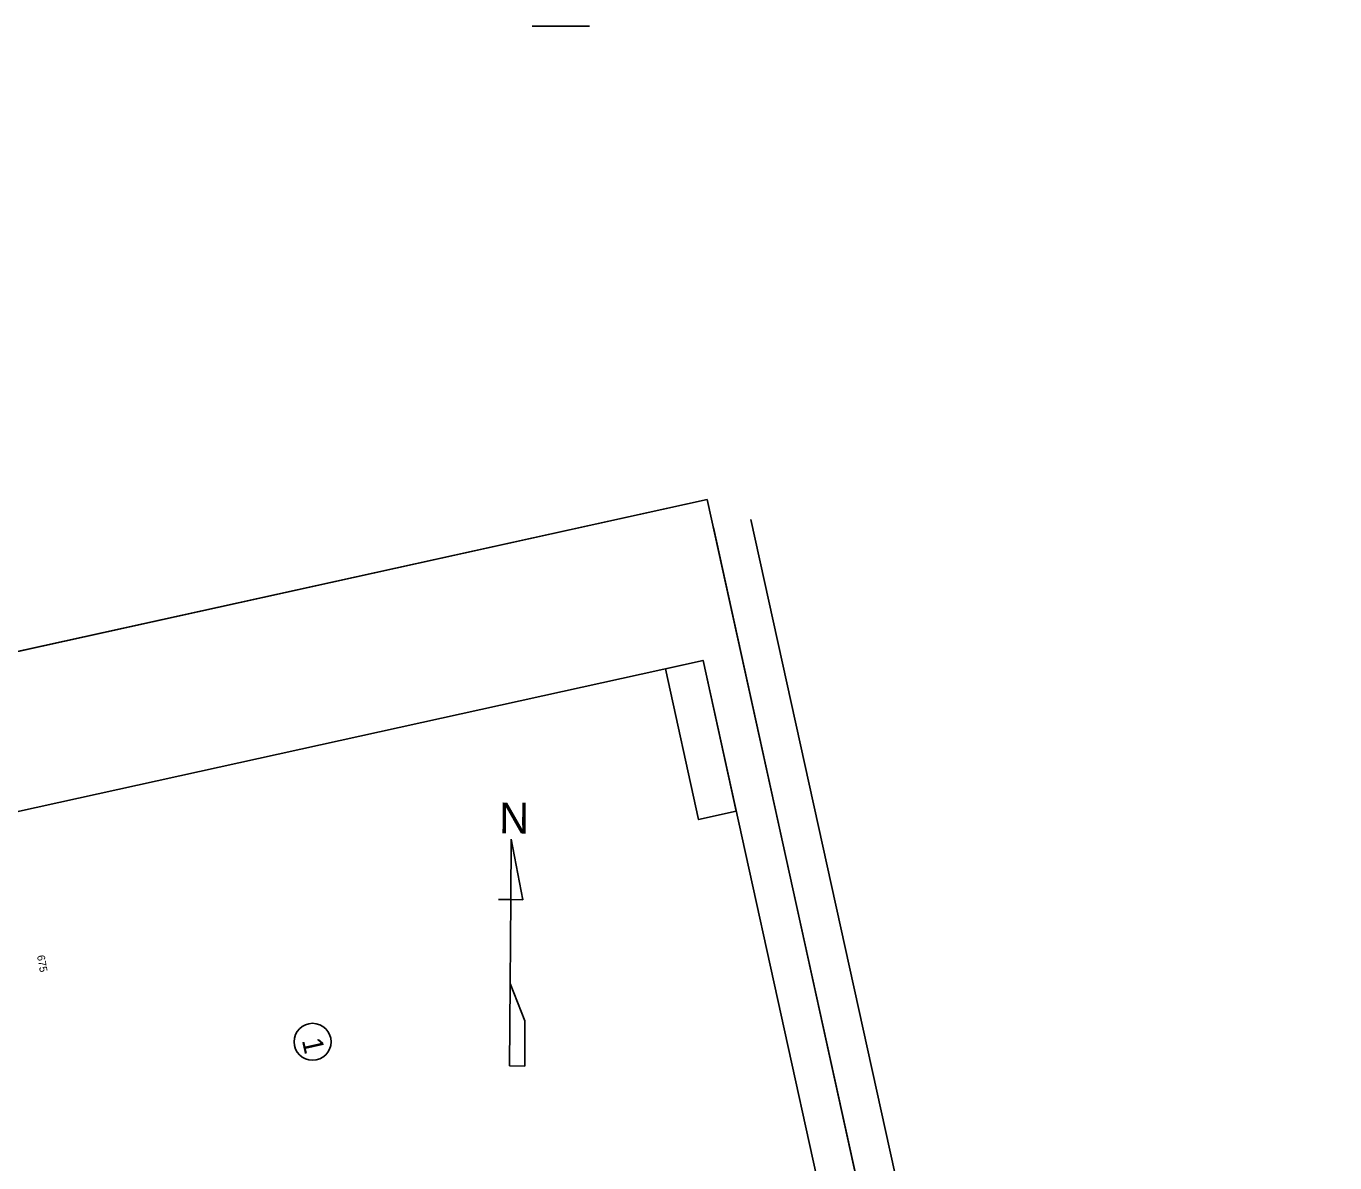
# Model space of a CAD drawing. Extents: x 2521558 to 2525396, y 882711 to 887632.
# Drawn here: x 2523699 to 2525396, y 885971 to 887444 of the extents above; entities that cross this region are included whole.
import ezdxf

# ---------------------------------------------------------------- set-up
doc = ezdxf.new("R2010")
doc.units = 0
for name, color, linetype in [('RD_EX_H2O', 7, 'Continuous'), ('RD_HC_TX_Sta50', 7, 'Continuous'), ('RD_SHT_Bndy', 7, 'Continuous'), ('RD_SHT_IplotShp', 7, 'Continuous'), ('RD_SHT_Snap', 7, 'Continuous'), ('RD_Sketch3', 7, 'Continuous')]:
    doc.layers.add(name, color=color, linetype=linetype)

msp = doc.modelspace()

# ---------------------------------------------------------------- linework, layer by layer
at = {"layer": 'RD_EX_H2O'}
msp.add_line((2524429.3, 887443.8), (2524354.9, 887443.8), dxfattribs=at)
at = {"layer": 'RD_SHT_Bndy'}
for p, q in [((2525395.7, 883367), (2524638.7, 886804.6)), ((2525346.9, 883356.2), (2524589.9, 886793.9)), ((2524576.6, 886621.8), (2522525.7, 886170.2)), ((2525297, 883350.2), (2524576.6, 886621.8))]:
    msp.add_line(p, q, dxfattribs=at)
msp.add_lwpolyline([(2524527.8, 886610.9), (2524576.6, 886621.7), (2524619.6, 886426.4), (2524570.8, 886415.6)], close=True, dxfattribs=at)
at = {"layer": 'RD_SHT_IplotShp'}
msp.add_lwpolyline([(2524581.9, 886830.2), (2525354.4, 883322.2), (2523205.9, 882849.1), (2522433.4, 886357.1)], close=True, dxfattribs=at)
at = {"layer": 'RD_SHT_Snap'}
msp.add_line((2522433.4, 886357.1), (2524581.9, 886830.2), dxfattribs=at)
at = {"layer": 'RD_Sketch3'}
for p, q in [((2524327.8, 886390.2), (2524327.2, 886311.8)), ((2524342.9, 886311.7), (2524327.8, 886390.2)), ((2524327.8, 886390.2), (2524327.8, 886390.2)), ((2524311.5, 886311.9), (2524327.2, 886311.8)), ((2524326.4, 886203), (2524327.2, 886311.8)), ((2524327.2, 886311.8), (2524342.9, 886311.7)), ((2524342.9, 886311.7), (2524342.9, 886312.6)), ((2524326.4, 886203), (2524325.7, 886096.2)), ((2524345.7, 886154.8), (2524326.4, 886203)), ((2524345.3, 886096), (2524345.7, 886155.4)), ((2524345.7, 886155.4), (2524345.7, 886154.8)), ((2524325.7, 886096.2), (2524345.3, 886096))]:
    msp.add_line(p, q, dxfattribs=at)
msp.add_circle((2524070.3, 886127.5), 24, dxfattribs=at)

# ---------------------------------------------------------------- texts
at = {"layer": 'RD_HC_TX_Sta50'}
msp.add_text('675', height=10, rotation=280.3595, dxfattribs=at).set_placement((2523712.9, 886239))
at = {"layer": 'RD_Sketch3'}
for s, height, rotation, p in [('N', 40, 359.5841, (2524312.1, 886397.7)), ('1', 26.4, 282.6622, (2524056.3, 886129.5))]:
    msp.add_text(s, height=height, rotation=rotation, dxfattribs=at).set_placement(p)

doc.saveas('drawing.dxf')
